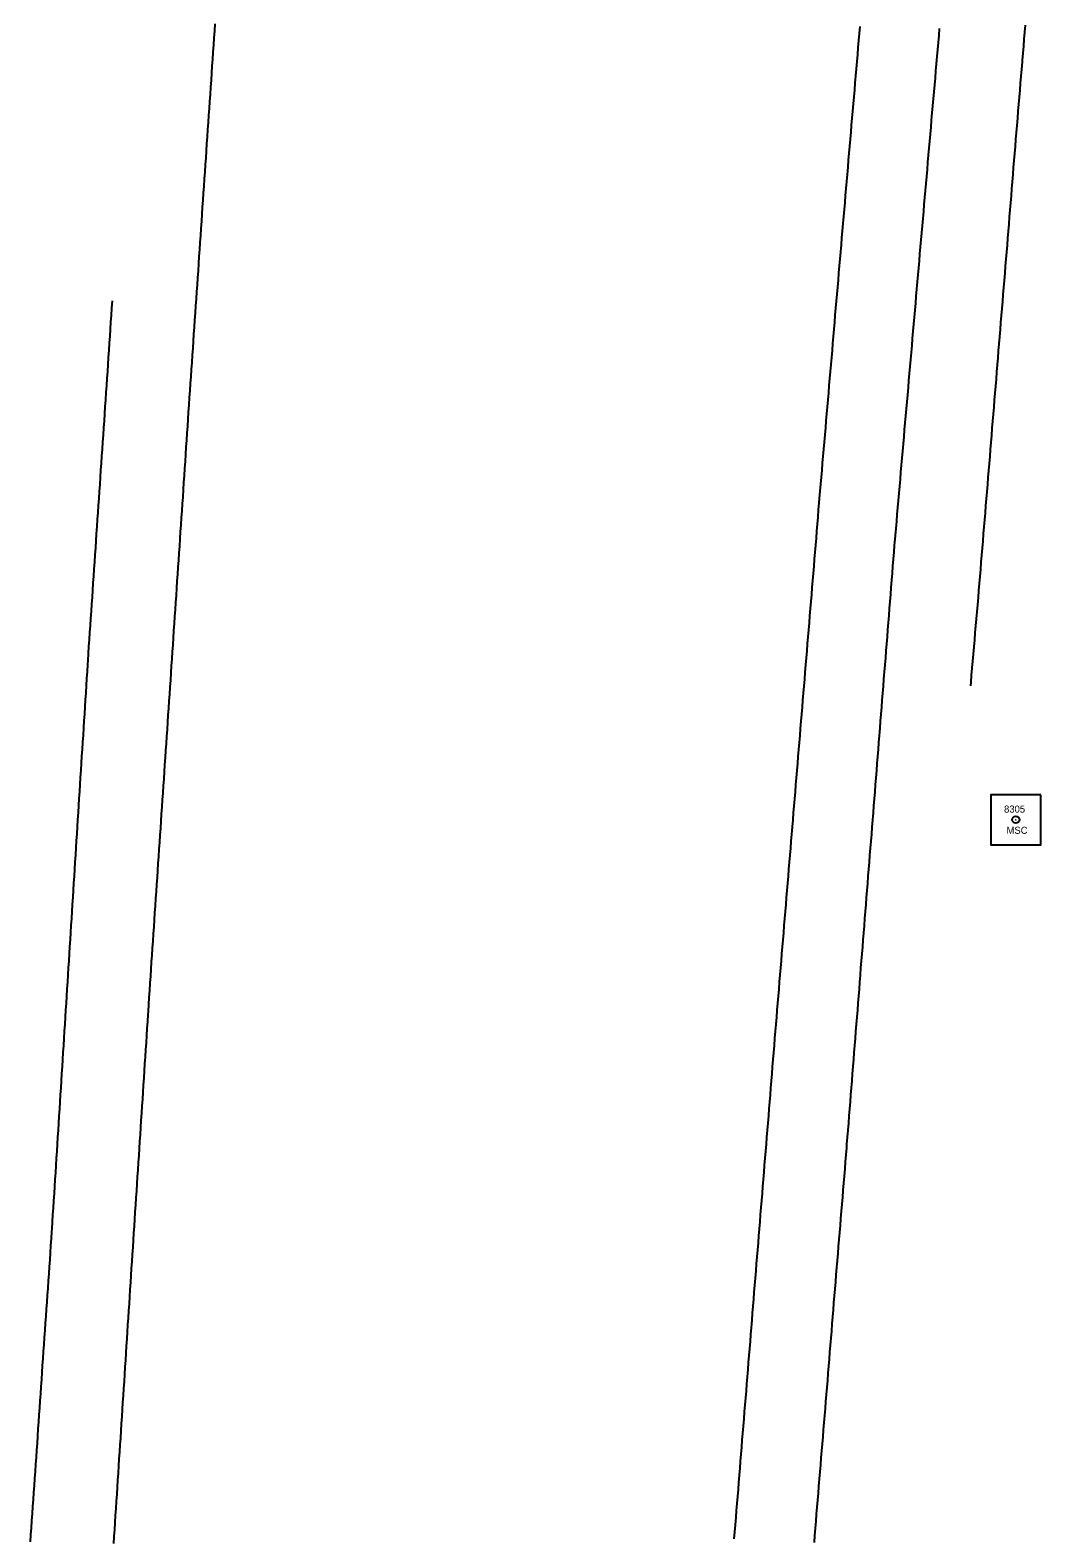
# Model space of a CAD drawing. Extents: x 205929 to 2357175, y -1785700 to 846739.
# Drawn here: x 2023451.6 to 2023594.5, y 809932.1 to 810145.3 of the extents above; entities that cross this region are included whole.
import ezdxf

# ---------------------------------------------------------------- set-up
doc = ezdxf.new("R2010")
doc.units = 0
for name, color, linetype in [('RD_HC_Survey', 7, 'Continuous'), ('RD_HC_txCode', 7, 'Continuous'), ('RD_Sketch1', 7, 'Continuous'), ('RD_SMD_Locator', 7, 'Continuous')]:
    doc.layers.add(name, color=color, linetype=linetype)

msp = doc.modelspace()

# ---------------------------------------------------------------- linework, layer by layer
at = {"layer": 'RD_HC_Survey'}
msp.add_lwpolyline([(2023594.49, 810037.19), (2023587.42, 810037.19), (2023587.42, 810030.12), (2023594.49, 810030.12)], close=True, dxfattribs=at)
msp.add_circle((2023590.96, 810033.66), 0.5, dxfattribs=at)
at = {"layer": 'RD_Sketch1'}
for points in [[(2023477.72, 810146.21), (2023477.65, 810145.21), (2023477.58, 810144.21), (2023477.52, 810143.22), (2023477.52, 810143.22), (2023477.45, 810142.22), (2023477.38, 810141.22), (2023477.31, 810140.22), (2023477.24, 810139.23), (2023477.18, 810138.23), (2023477.11, 810137.23), (2023477.04, 810136.23), (2023476.97, 810135.24), (2023476.9, 810134.24), (2023476.83, 810133.24), (2023476.77, 810132.24), (2023476.7, 810131.25), (2023476.63, 810130.25), (2023476.56, 810129.25), (2023476.49, 810128.26), (2023476.43, 810127.26), (2023476.36, 810126.26), (2023476.29, 810125.26), (2023476.22, 810124.27), (2023476.15, 810123.27), (2023476.09, 810122.27), (2023476.02, 810121.27), (2023475.95, 810120.28), (2023475.88, 810119.28), (2023475.81, 810118.28), (2023475.74, 810117.28), (2023475.68, 810116.29), (2023475.61, 810115.29), (2023475.54, 810114.29), (2023475.47, 810113.29), (2023475.4, 810112.3), (2023475.34, 810111.3), (2023475.27, 810110.3), (2023475.2, 810109.31), (2023475.13, 810108.31), (2023475.06, 810107.31), (2023475, 810106.31), (2023474.93, 810105.32), (2023474.86, 810104.32), (2023474.79, 810103.32), (2023474.72, 810102.32), (2023474.66, 810101.33), (2023474.59, 810100.33), (2023474.52, 810099.33), (2023474.45, 810098.33), (2023474.38, 810097.34), (2023474.31, 810096.34), (2023474.25, 810095.34), (2023474.18, 810094.34), (2023474.11, 810093.35), (2023474.04, 810092.31), (2023473.97, 810091.31), (2023473.91, 810090.32), (2023473.84, 810089.32), (2023473.77, 810088.32), (2023473.7, 810087.32), (2023473.64, 810086.33), (2023473.57, 810085.33), (2023473.5, 810084.33), (2023473.44, 810083.33), (2023473.37, 810082.34), (2023473.3, 810081.34), (2023473.23, 810080.34), (2023473.17, 810079.34), (2023473.17, 810079.34), (2023473.1, 810078.35), (2023473.03, 810077.35), (2023472.97, 810076.35), (2023472.9, 810075.35), (2023472.83, 810074.36), (2023472.77, 810073.36), (2023472.7, 810072.36), (2023472.63, 810071.36), (2023472.56, 810070.37), (2023472.5, 810069.37), (2023472.43, 810068.37), (2023472.36, 810067.37), (2023472.3, 810066.38), (2023472.23, 810065.38), (2023472.16, 810064.38), (2023472.1, 810063.38), (2023472.03, 810062.39), (2023471.96, 810061.39), (2023471.89, 810060.39), (2023471.83, 810059.39), (2023471.76, 810058.4), (2023471.69, 810057.4), (2023471.63, 810056.4), (2023471.56, 810055.41), (2023471.49, 810054.41), (2023471.43, 810053.41), (2023471.36, 810052.41), (2023471.29, 810051.42), (2023471.22, 810050.42), (2023471.16, 810049.42), (2023471.09, 810048.42), (2023471.02, 810047.43), (2023470.96, 810046.43), (2023470.89, 810045.43), (2023470.82, 810044.43), (2023470.75, 810043.44), (2023470.69, 810042.44), (2023470.62, 810041.44), (2023470.55, 810040.44), (2023470.49, 810039.45), (2023470.42, 810038.45), (2023470.35, 810037.45), (2023470.29, 810036.45), (2023470.22, 810035.46), (2023470.15, 810034.46), (2023470.08, 810033.46), (2023470.02, 810032.46), (2023469.95, 810031.47), (2023469.88, 810030.47), (2023469.82, 810029.47), (2023469.75, 810028.47), (2023469.68, 810027.48), (2023469.62, 810026.48), (2023469.55, 810025.48), (2023469.48, 810024.48), (2023469.41, 810023.49), (2023469.35, 810022.49), (2023469.28, 810021.49), (2023469.21, 810020.49), (2023469.15, 810019.5), (2023469.08, 810018.5), (2023469.01, 810017.5), (2023468.94, 810016.5), (2023468.88, 810015.51), (2023468.88, 810015.51), (2023468.81, 810014.51), (2023468.74, 810013.51), (2023468.68, 810012.51), (2023468.61, 810011.52), (2023468.54, 810010.52), (2023468.48, 810009.52), (2023468.41, 810008.52), (2023468.34, 810007.53), (2023468.27, 810006.53), (2023468.25, 810006.11), (2023468.18, 810005.11), (2023468.12, 810004.11), (2023468.05, 810003.12), (2023467.99, 810002.12), (2023467.92, 810001.12), (2023467.86, 810000.12), (2023467.79, 809999.13), (2023467.73, 809998.13), (2023467.66, 809997.13), (2023467.6, 809996.13), (2023467.53, 809995.14), (2023467.47, 809994.14), (2023467.4, 809993.14), (2023467.34, 809992.14), (2023467.27, 809991.14), (2023467.21, 809990.15), (2023467.14, 809989.15), (2023467.08, 809988.15), (2023467.01, 809987.15), (2023466.95, 809986.16), (2023466.89, 809985.16), (2023466.82, 809984.16), (2023466.76, 809983.16), (2023466.69, 809982.16), (2023466.63, 809981.17), (2023466.56, 809980.17), (2023466.5, 809979.17), (2023466.43, 809978.17), (2023466.37, 809977.18), (2023466.3, 809976.18), (2023466.24, 809975.18), (2023466.17, 809974.18), (2023466.11, 809973.19), (2023466.04, 809972.19), (2023465.98, 809971.19), (2023465.91, 809970.19), (2023465.85, 809969.19), (2023465.78, 809968.2), (2023465.72, 809967.2), (2023465.65, 809966.2), (2023465.59, 809965.2), (2023465.52, 809964.21), (2023465.46, 809963.21), (2023465.39, 809962.21), (2023465.33, 809961.21), (2023465.26, 809960.22), (2023465.2, 809959.22), (2023465.14, 809958.22), (2023465.07, 809957.22), (2023465.01, 809956.22), (2023464.94, 809955.23), (2023464.88, 809954.23), (2023464.81, 809953.23), (2023464.75, 809952.23), (2023464.75, 809952.23), (2023464.68, 809951.24), (2023464.62, 809950.24), (2023464.55, 809949.24), (2023464.49, 809948.24), (2023464.42, 809947.25), (2023464.36, 809946.25), (2023464.29, 809945.25), (2023464.23, 809944.25), (2023464.16, 809943.25), (2023464.1, 809942.26), (2023464.03, 809941.26), (2023463.97, 809940.26), (2023463.9, 809939.26), (2023463.84, 809938.27), (2023463.77, 809937.27), (2023463.71, 809936.27), (2023463.64, 809935.27), (2023463.58, 809934.28), (2023463.51, 809933.28), (2023463.45, 809932.28), (2023463.39, 809931.28)], [(2023568.9, 810145.84), (2023568.81, 810144.84), (2023568.73, 810143.84), (2023568.64, 810142.85), (2023568.55, 810141.85), (2023568.47, 810140.86), (2023568.38, 810139.86), (2023568.3, 810138.86), (2023568.21, 810137.87), (2023568.13, 810136.87), (2023568.04, 810135.88), (2023567.96, 810134.88), (2023567.87, 810133.88), (2023567.79, 810132.89), (2023567.7, 810131.89), (2023567.61, 810130.9), (2023567.53, 810129.9), (2023567.44, 810128.9), (2023567.36, 810127.91), (2023567.27, 810126.91), (2023567.19, 810125.92), (2023567.1, 810124.92), (2023567.02, 810123.92), (2023566.93, 810122.93), (2023566.85, 810121.93), (2023566.76, 810120.94), (2023566.68, 810119.94), (2023566.59, 810118.94), (2023566.5, 810117.95), (2023566.42, 810116.95), (2023566.33, 810115.96), (2023566.25, 810114.96), (2023566.16, 810113.96), (2023566.08, 810112.97), (2023565.99, 810111.97), (2023565.91, 810110.98), (2023565.82, 810109.98), (2023565.74, 810108.98), (2023565.65, 810107.99), (2023565.56, 810106.99), (2023565.48, 810106), (2023565.39, 810105), (2023565.31, 810104), (2023565.22, 810103.01), (2023565.14, 810102.01), (2023565.05, 810101.02), (2023564.97, 810100.02), (2023564.88, 810099.02), (2023564.8, 810098.03), (2023564.71, 810097.03), (2023564.62, 810096.04), (2023564.54, 810095.04), (2023564.45, 810094.04), (2023564.37, 810093.05), (2023564.28, 810092.05), (2023564.2, 810091.06), (2023564.11, 810090.06), (2023564.03, 810089.06), (2023563.94, 810088.07), (2023563.86, 810087.07), (2023563.77, 810086.08), (2023563.68, 810085.08), (2023563.6, 810084.08), (2023563.51, 810083.09), (2023563.43, 810082.09), (2023563.43, 810082.09), (2023563.34, 810081.1), (2023563.26, 810080.1), (2023563.17, 810079.1), (2023563.12, 810078.46), (2023563.03, 810077.46), (2023562.95, 810076.46), (2023562.87, 810075.47), (2023562.79, 810074.47), (2023562.71, 810073.47), (2023562.62, 810072.48), (2023562.54, 810071.48), (2023562.46, 810070.48), (2023562.38, 810069.49), (2023562.29, 810068.49), (2023562.21, 810067.5), (2023562.13, 810066.5), (2023562.05, 810065.5), (2023561.96, 810064.51), (2023561.88, 810063.51), (2023561.8, 810062.51), (2023561.72, 810061.52), (2023561.64, 810060.52), (2023561.55, 810059.53), (2023561.47, 810058.53), (2023561.39, 810057.53), (2023561.31, 810056.54), (2023561.22, 810055.54), (2023561.14, 810054.54), (2023561.06, 810053.55), (2023560.98, 810052.55), (2023560.9, 810051.56), (2023560.81, 810050.56), (2023560.73, 810049.56), (2023560.65, 810048.57), (2023560.57, 810047.57), (2023560.48, 810046.57), (2023560.4, 810045.58), (2023560.32, 810044.58), (2023560.24, 810043.59), (2023560.16, 810042.59), (2023560.07, 810041.59), (2023559.99, 810040.6), (2023559.91, 810039.6), (2023559.83, 810038.6), (2023559.74, 810037.61), (2023559.66, 810036.61), (2023559.58, 810035.62), (2023559.5, 810034.62), (2023559.41, 810033.62), (2023559.33, 810032.63), (2023559.25, 810031.63), (2023559.17, 810030.63), (2023559.09, 810029.64), (2023559, 810028.64), (2023558.92, 810027.65), (2023558.84, 810026.65), (2023558.76, 810025.65), (2023558.67, 810024.66), (2023558.59, 810023.66), (2023558.51, 810022.66), (2023558.43, 810021.67), (2023558.35, 810020.67), (2023558.26, 810019.68), (2023558.18, 810018.68), (2023558.18, 810018.68), (2023558.1, 810017.68), (2023558.02, 810016.69), (2023557.93, 810015.69), (2023557.85, 810014.69), (2023557.77, 810013.7), (2023557.69, 810012.7), (2023557.61, 810011.7), (2023557.52, 810010.71), (2023557.44, 810009.71), (2023557.36, 810008.72), (2023557.28, 810007.72), (2023557.19, 810006.72), (2023557.11, 810005.73), (2023557.03, 810004.73), (2023556.95, 810003.73), (2023556.86, 810002.74), (2023556.78, 810001.74), (2023556.7, 810000.75), (2023556.62, 809999.75), (2023556.53, 809998.73), (2023556.45, 809997.74), (2023556.37, 809996.74), (2023556.29, 809995.74), (2023556.21, 809994.75), (2023556.13, 809993.75), (2023556.05, 809992.75), (2023555.97, 809991.76), (2023555.89, 809990.76), (2023555.81, 809989.76), (2023555.72, 809988.77), (2023555.64, 809987.77), (2023555.56, 809986.78), (2023555.48, 809985.78), (2023555.4, 809984.78), (2023555.32, 809983.79), (2023555.24, 809982.79), (2023555.16, 809981.79), (2023555.08, 809980.8), (2023555, 809979.8), (2023554.91, 809978.8), (2023554.83, 809977.81), (2023554.75, 809976.81), (2023554.67, 809975.81), (2023554.59, 809974.82), (2023554.51, 809973.82), (2023554.43, 809972.83), (2023554.35, 809971.83), (2023554.27, 809970.83), (2023554.19, 809969.84), (2023554.11, 809968.84), (2023554.02, 809967.84), (2023553.94, 809966.85), (2023553.86, 809965.85), (2023553.78, 809964.85), (2023553.7, 809963.86), (2023553.62, 809962.86), (2023553.54, 809961.86), (2023553.46, 809960.87), (2023553.38, 809959.87), (2023553.3, 809958.87), (2023553.21, 809957.88), (2023553.13, 809956.88), (2023553.05, 809955.89), (2023552.97, 809954.89), (2023552.97, 809954.89), (2023552.89, 809953.89), (2023552.81, 809952.9), (2023552.73, 809951.9), (2023552.65, 809950.9), (2023552.57, 809949.91), (2023552.49, 809948.91), (2023552.41, 809947.91), (2023552.32, 809946.92), (2023552.24, 809945.92), (2023552.16, 809944.92), (2023552.08, 809943.93), (2023552, 809942.93), (2023551.92, 809941.94), (2023551.84, 809940.94), (2023551.76, 809939.94), (2023551.68, 809938.95), (2023551.6, 809937.95), (2023551.51, 809936.95), (2023551.43, 809935.96), (2023551.35, 809934.96), (2023551.27, 809933.96), (2023551.19, 809932.97), (2023551.11, 809931.97)], [(2023580.14, 810145.55), (2023580.05, 810144.56), (2023579.97, 810143.56), (2023579.88, 810142.56), (2023579.79, 810141.57), (2023579.71, 810140.57), (2023579.62, 810139.58), (2023579.53, 810138.58), (2023579.45, 810137.58), (2023579.36, 810136.59), (2023579.27, 810135.59), (2023579.18, 810134.6), (2023579.1, 810133.6), (2023579.01, 810132.6), (2023578.92, 810131.61), (2023578.84, 810130.61), (2023578.75, 810129.62), (2023578.66, 810128.62), (2023578.58, 810127.62), (2023578.49, 810126.63), (2023578.4, 810125.63), (2023578.32, 810124.64), (2023578.23, 810123.64), (2023578.14, 810122.64), (2023578.06, 810121.65), (2023577.97, 810120.65), (2023577.88, 810119.66), (2023577.8, 810118.66), (2023577.71, 810117.66), (2023577.62, 810116.67), (2023577.54, 810115.67), (2023577.45, 810114.68), (2023577.36, 810113.68), (2023577.28, 810112.69), (2023577.19, 810111.69), (2023577.1, 810110.69), (2023577.02, 810109.7), (2023576.93, 810108.7), (2023576.84, 810107.71), (2023576.76, 810106.71), (2023576.67, 810105.71), (2023576.58, 810104.72), (2023576.5, 810103.72), (2023576.41, 810102.73), (2023576.32, 810101.73), (2023576.24, 810100.73), (2023576.15, 810099.74), (2023576.06, 810098.74), (2023575.98, 810097.75), (2023575.89, 810096.75), (2023575.8, 810095.75), (2023575.72, 810094.76), (2023575.63, 810093.76), (2023575.54, 810092.77), (2023575.46, 810091.77), (2023575.37, 810090.77), (2023575.28, 810089.78), (2023575.19, 810088.78), (2023575.11, 810087.79), (2023575.02, 810086.79), (2023574.93, 810085.79), (2023574.85, 810084.8), (2023574.76, 810083.8), (2023574.67, 810082.81), (2023574.59, 810081.81), (2023574.59, 810081.81), (2023574.5, 810080.82), (2023574.41, 810079.82), (2023574.33, 810078.82), (2023574.24, 810077.83), (2023574.15, 810076.83), (2023574.07, 810075.84), (2023573.98, 810074.84), (2023573.89, 810073.84), (2023573.81, 810072.85), (2023573.78, 810072.49), (2023573.7, 810071.49), (2023573.62, 810070.5), (2023573.54, 810069.5), (2023573.46, 810068.5), (2023573.38, 810067.51), (2023573.3, 810066.51), (2023573.22, 810065.51), (2023573.14, 810064.52), (2023573.06, 810063.52), (2023572.98, 810062.52), (2023572.9, 810061.53), (2023572.83, 810060.53), (2023572.75, 810059.53), (2023572.67, 810058.54), (2023572.59, 810057.54), (2023572.51, 810056.54), (2023572.43, 810055.55), (2023572.35, 810054.55), (2023572.27, 810053.55), (2023572.19, 810052.56), (2023572.11, 810051.56), (2023572.03, 810050.56), (2023571.95, 810049.57), (2023571.87, 810048.57), (2023571.8, 810047.57), (2023571.72, 810046.58), (2023571.64, 810045.58), (2023571.56, 810044.58), (2023571.48, 810043.59), (2023571.4, 810042.59), (2023571.32, 810041.59), (2023571.24, 810040.6), (2023571.16, 810039.6), (2023571.08, 810038.6), (2023571, 810037.61), (2023570.92, 810036.61), (2023570.85, 810035.61), (2023570.77, 810034.62), (2023570.69, 810033.62), (2023570.61, 810032.62), (2023570.53, 810031.63), (2023570.45, 810030.63), (2023570.37, 810029.63), (2023570.29, 810028.64), (2023570.21, 810027.64), (2023570.13, 810026.64), (2023570.05, 810025.65), (2023569.97, 810024.65), (2023569.89, 810023.65), (2023569.82, 810022.66), (2023569.74, 810021.66), (2023569.66, 810020.66), (2023569.58, 810019.67), (2023569.5, 810018.67), (2023569.5, 810018.67), (2023569.42, 810017.67), (2023569.34, 810016.68), (2023569.26, 810015.68), (2023569.18, 810014.68), (2023569.1, 810013.69), (2023569.02, 810012.69), (2023568.94, 810011.69), (2023568.87, 810010.7), (2023568.79, 810009.7), (2023568.71, 810008.7), (2023568.63, 810007.71), (2023568.55, 810006.71), (2023568.47, 810005.71), (2023568.39, 810004.72), (2023568.31, 810003.72), (2023568.23, 810002.72), (2023568.15, 810001.73), (2023568.07, 810000.73), (2023567.99, 809999.73), (2023567.91, 809998.74), (2023567.84, 809997.74), (2023567.76, 809996.74), (2023567.68, 809995.75), (2023567.6, 809994.75), (2023567.52, 809993.75), (2023567.44, 809992.76), (2023567.36, 809991.76), (2023567.28, 809990.76), (2023567.2, 809989.77), (2023567.12, 809988.77), (2023567.04, 809987.77), (2023567, 809987.25), (2023566.92, 809986.25), (2023566.84, 809985.26), (2023566.76, 809984.26), (2023566.67, 809983.26), (2023566.59, 809982.27), (2023566.51, 809981.27), (2023566.43, 809980.27), (2023566.35, 809979.28), (2023566.27, 809978.28), (2023566.18, 809977.28), (2023566.1, 809976.29), (2023566.02, 809975.29), (2023565.94, 809974.3), (2023565.86, 809973.3), (2023565.78, 809972.3), (2023565.69, 809971.31), (2023565.61, 809970.31), (2023565.53, 809969.31), (2023565.45, 809968.32), (2023565.37, 809967.32), (2023565.29, 809966.32), (2023565.2, 809965.33), (2023565.12, 809964.33), (2023565.04, 809963.34), (2023564.96, 809962.34), (2023564.88, 809961.34), (2023564.8, 809960.35), (2023564.71, 809959.35), (2023564.63, 809958.35), (2023564.55, 809957.36), (2023564.47, 809956.36), (2023564.39, 809955.37), (2023564.39, 809955.37), (2023564.31, 809954.37), (2023564.22, 809953.37), (2023564.14, 809952.38), (2023564.06, 809951.38), (2023563.98, 809950.38), (2023563.9, 809949.39), (2023563.82, 809948.39), (2023563.73, 809947.39), (2023563.65, 809946.4), (2023563.57, 809945.4), (2023563.49, 809944.41), (2023563.41, 809943.41), (2023563.33, 809942.41), (2023563.24, 809941.42), (2023563.16, 809940.42), (2023563.08, 809939.42), (2023563, 809938.43), (2023562.92, 809937.43), (2023562.84, 809936.43), (2023562.75, 809935.44), (2023562.67, 809934.44), (2023562.59, 809933.45), (2023562.51, 809932.45), (2023562.43, 809931.45)], [(2023592.28, 810146.04), (2023592.19, 810145.04), (2023592.11, 810144.04), (2023592.02, 810143.05), (2023591.94, 810142.05), (2023591.94, 810142.05), (2023591.85, 810141.06), (2023591.83, 810140.82), (2023591.75, 810139.82), (2023591.67, 810138.82), (2023591.58, 810137.83), (2023591.5, 810136.83), (2023591.42, 810135.84), (2023591.34, 810134.84), (2023591.26, 810133.84), (2023591.18, 810132.85), (2023591.09, 810131.85), (2023591.01, 810130.85), (2023590.93, 810129.86), (2023590.85, 810128.86), (2023590.77, 810127.87), (2023590.69, 810126.87), (2023590.6, 810125.87), (2023590.52, 810124.88), (2023590.44, 810123.88), (2023590.36, 810122.88), (2023590.28, 810121.89), (2023590.2, 810120.89), (2023590.11, 810119.89), (2023590.03, 810118.9), (2023589.95, 810117.9), (2023589.87, 810116.91), (2023589.79, 810115.91), (2023589.71, 810114.91), (2023589.62, 810113.92), (2023589.54, 810112.92), (2023589.46, 810111.92), (2023589.38, 810110.93), (2023589.3, 810109.93), (2023589.22, 810108.94), (2023589.13, 810107.94), (2023589.05, 810106.94), (2023588.97, 810105.95), (2023588.89, 810104.95), (2023588.81, 810103.95), (2023588.73, 810102.96), (2023588.64, 810101.96), (2023588.56, 810100.97), (2023588.48, 810099.97), (2023588.4, 810098.97), (2023588.32, 810097.98), (2023588.24, 810096.98), (2023588.16, 810095.98), (2023588.07, 810094.99), (2023587.99, 810093.99), (2023587.91, 810092.99), (2023587.83, 810092), (2023587.75, 810091), (2023587.67, 810090.01), (2023587.58, 810089.01), (2023587.5, 810088.01), (2023587.42, 810087.02), (2023587.34, 810086.02), (2023587.26, 810085.02), (2023587.18, 810084.03), (2023587.09, 810083.03), (2023587.01, 810082.04), (2023586.93, 810081.04), (2023586.85, 810080.04), (2023586.77, 810079.05), (2023586.77, 810079.05), (2023586.69, 810078.05), (2023586.6, 810077.05), (2023586.52, 810076.06), (2023586.44, 810075.06), (2023586.36, 810074.07), (2023586.28, 810073.07), (2023586.2, 810072.07), (2023586.11, 810071.08), (2023586.03, 810070.08), (2023585.95, 810069.04), (2023585.86, 810068.05), (2023585.78, 810067.05), (2023585.69, 810066.05), (2023585.61, 810065.06), (2023585.52, 810064.06), (2023585.43, 810063.07), (2023585.35, 810062.07), (2023585.26, 810061.07), (2023585.18, 810060.08), (2023585.09, 810059.08), (2023585.01, 810058.09), (2023584.92, 810057.09), (2023584.84, 810056.09), (2023584.75, 810055.1), (2023584.66, 810054.1), (2023584.58, 810053.1), (2023584.53, 810052.58)], [(2023463.2, 810107.02), (2023463.13, 810106.02), (2023463.06, 810105.02), (2023462.99, 810104.03), (2023462.93, 810103.03), (2023462.86, 810102.03), (2023462.79, 810101.03), (2023462.72, 810100.04), (2023462.66, 810099.04), (2023462.59, 810098.04), (2023462.52, 810097.04), (2023462.45, 810096.05), (2023462.38, 810095.05), (2023462.32, 810094.05), (2023462.25, 810093.05), (2023462.18, 810092.06), (2023462.11, 810091.06), (2023462.05, 810090.06), (2023461.98, 810089.06), (2023461.91, 810088.07), (2023461.84, 810087.07), (2023461.78, 810086.07), (2023461.71, 810085.07), (2023461.64, 810084.08), (2023461.57, 810083.08), (2023461.51, 810082.08), (2023461.44, 810081.08), (2023461.37, 810080.09), (2023461.3, 810079.09), (2023461.23, 810078.09), (2023461.17, 810077.09), (2023461.1, 810076.1), (2023461.03, 810075.1), (2023460.96, 810074.1), (2023460.9, 810073.1), (2023460.83, 810072.11), (2023460.76, 810071.11), (2023460.69, 810070.11), (2023460.63, 810069.11), (2023460.56, 810068.12), (2023460.49, 810067.12), (2023460.42, 810066.12), (2023460.36, 810065.12), (2023460.29, 810064.13), (2023460.22, 810063.13), (2023460.15, 810062.13), (2023460.08, 810061.13), (2023460.02, 810060.14), (2023459.95, 810059.14), (2023459.88, 810058.14), (2023459.81, 810057.14), (2023459.75, 810056.15), (2023459.71, 810055.61), (2023459.65, 810054.61), (2023459.58, 810053.61), (2023459.52, 810052.62), (2023459.46, 810051.62), (2023459.39, 810050.62), (2023459.33, 810049.62), (2023459.27, 810048.62), (2023459.21, 810047.63), (2023459.14, 810046.63), (2023459.08, 810045.63), (2023459.02, 810044.63), (2023458.95, 810043.64), (2023458.95, 810043.64), (2023458.89, 810042.64), (2023458.83, 810041.64), (2023458.76, 810040.64), (2023458.7, 810039.64), (2023458.64, 810038.65), (2023458.57, 810037.65), (2023458.51, 810036.65), (2023458.45, 810035.65), (2023458.39, 810034.66), (2023458.32, 810033.66), (2023458.26, 810032.66), (2023458.2, 810031.66), (2023458.13, 810030.66), (2023458.07, 810029.67), (2023458.01, 810028.67), (2023457.94, 810027.67), (2023457.88, 810026.67), (2023457.82, 810025.68), (2023457.75, 810024.68), (2023457.69, 810023.68), (2023457.63, 810022.68), (2023457.57, 810021.68), (2023457.5, 810020.69), (2023457.44, 810019.69), (2023457.38, 810018.69), (2023457.31, 810017.69), (2023457.25, 810016.7), (2023457.19, 810015.7), (2023457.12, 810014.7), (2023457.06, 810013.7), (2023457, 810012.7), (2023456.93, 810011.71), (2023456.87, 810010.71), (2023456.81, 810009.71), (2023456.75, 810008.71), (2023456.68, 810007.72), (2023456.62, 810006.72), (2023456.56, 810005.72), (2023456.49, 810004.72), (2023456.43, 810003.73), (2023456.37, 810002.73), (2023456.3, 810001.73), (2023456.24, 810000.73), (2023456.18, 809999.73), (2023456.12, 809998.74), (2023456.05, 809997.74), (2023455.99, 809996.74), (2023455.93, 809995.74), (2023455.86, 809994.75), (2023455.8, 809993.75), (2023455.74, 809992.75), (2023455.67, 809991.75), (2023455.61, 809990.75), (2023455.55, 809989.76), (2023455.48, 809988.76), (2023455.42, 809987.76), (2023455.36, 809986.76), (2023455.3, 809985.77), (2023455.23, 809984.77), (2023455.17, 809983.77), (2023455.11, 809982.77), (2023455.04, 809981.77), (2023454.98, 809980.78), (2023454.92, 809979.78), (2023454.92, 809979.78), (2023454.85, 809978.78), (2023454.79, 809977.78), (2023454.73, 809976.79), (2023454.66, 809975.79), (2023454.64, 809975.41), (2023454.57, 809974.42), (2023454.5, 809973.42), (2023454.43, 809972.42), (2023454.37, 809971.42), (2023454.3, 809970.43), (2023454.23, 809969.43), (2023454.16, 809968.43), (2023454.09, 809967.43), (2023454.02, 809966.44), (2023453.95, 809965.44), (2023453.88, 809964.44), (2023453.81, 809963.44), (2023453.75, 809962.45), (2023453.68, 809961.45), (2023453.61, 809960.45), (2023453.54, 809959.46), (2023453.47, 809958.46), (2023453.4, 809957.46), (2023453.33, 809956.46), (2023453.26, 809955.47), (2023453.19, 809954.47), (2023453.13, 809953.47), (2023453.06, 809952.47), (2023452.99, 809951.48), (2023452.92, 809950.48), (2023452.85, 809949.48), (2023452.78, 809948.48), (2023452.71, 809947.49), (2023452.64, 809946.49), (2023452.58, 809945.49), (2023452.51, 809944.49), (2023452.44, 809943.5), (2023452.37, 809942.5), (2023452.3, 809941.5), (2023452.23, 809940.5), (2023452.16, 809939.51), (2023452.09, 809938.51), (2023452.02, 809937.51), (2023451.96, 809936.52), (2023451.89, 809935.52), (2023451.82, 809934.52), (2023451.75, 809933.52), (2023451.68, 809932.53), (2023451.61, 809931.53)]]:
    msp.add_lwpolyline(points, dxfattribs=at)
at = {"layer": 'RD_SMD_Locator'}
msp.add_circle((2023590.96, 810033.66), 0.001, dxfattribs=at)

# ---------------------------------------------------------------- texts
at = {"layer": 'RD_HC_txCode'}
for s, p in [('8305', (2023589.29, 810034.66)), ('MSC', (2023589.64, 810031.66))]:
    msp.add_text(s, height=1, dxfattribs=at).set_placement(p)

doc.saveas('drawing.dxf')
